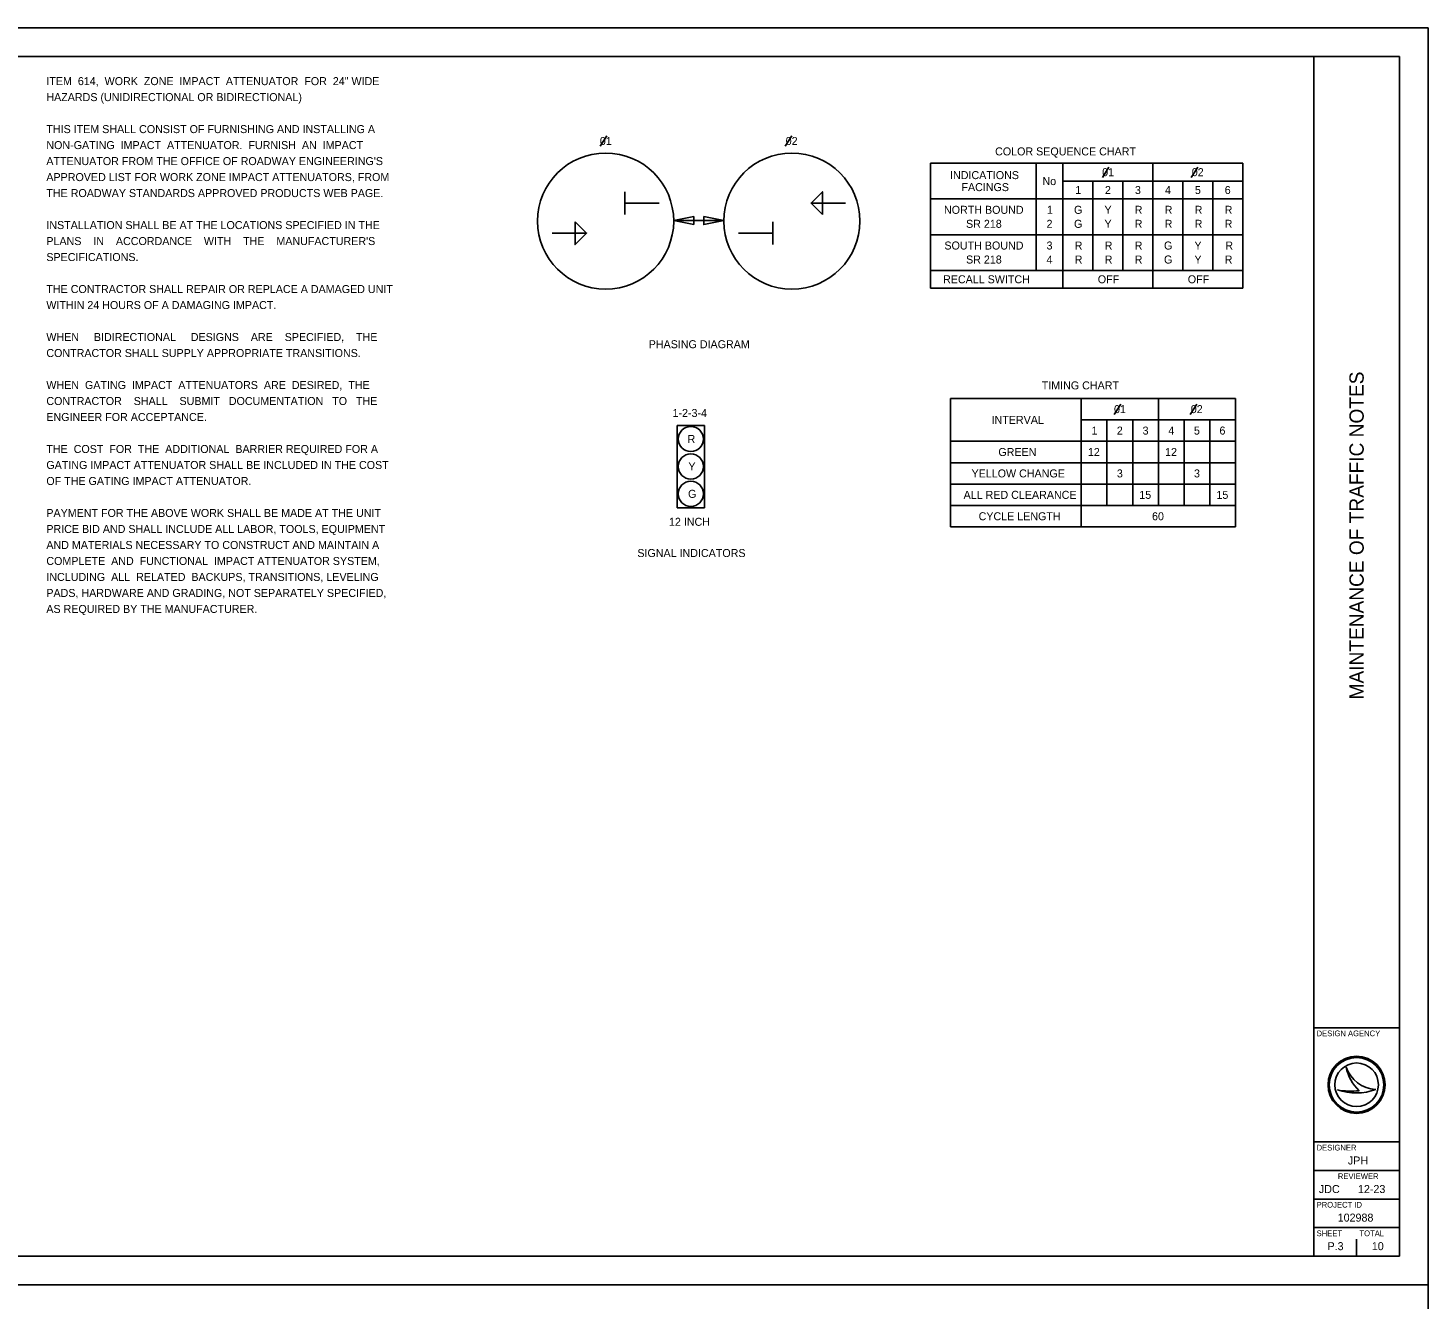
# Model space of a CAD drawing. Extents: x -188 to 680, y 0 to 880.
# Drawn here: x 190 to 680, y 435 to 880 of the extents above; entities that cross this region are included whole.
import ezdxf

# ---------------------------------------------------------------- set-up
doc = ezdxf.new("R2010")
doc.units = 0
for name, color, linetype in [('_CIVIL_CONSTRUCTION', 7, 'Continuous'), ('Default', 7, 'Continuous'), ('DR_X_Culvert', 7, 'Continuous'), ('GE_P_Alignment', 7, 'Continuous'), ('GE_P_Alignment_100_Bearings', 7, 'Continuous'), ('GE_P_Alignment_100_Cardinal_Points', 7, 'Continuous'), ('GE_P_Alignment_100_Curve_Data', 7, 'Continuous'), ('TX_X_10', 7, 'Continuous')]:
    doc.layers.add(name, color=color, linetype=linetype)

msp = doc.modelspace()

# ---------------------------------------------------------------- linework, layer by layer
at = {"layer": '_CIVIL_CONSTRUCTION'}
for points in [[(0, 440), (680, 440), (680, 880), (0, 880)], [(0, 0), (680, 0), (680, 440), (0, 440)]]:
    msp.add_lwpolyline(points, close=True, dxfattribs=at)
at = {"layer": 'Default'}
for p, q in [((505.84, 832.64), (505.84, 788.89)), ((505.84, 832.64), (615.22, 832.64)), ((542.84, 832.64), (542.84, 795.14)), ((552.22, 832.64), (552.22, 788.89)), ((583.72, 832.64), (583.72, 788.89)), ((615.22, 832.64), (615.22, 788.89)), ((615.22, 832.64), (615.22, 788.89)), ((552.22, 826.39), (615.22, 826.39)), ((562.72, 826.39), (562.72, 795.14)), ((573.22, 826.39), (573.22, 795.14)), ((594.22, 826.39), (594.22, 795.14)), ((604.72, 826.39), (604.72, 795.14)), ((505.84, 820.14), (615.22, 820.14)), ((505.84, 807.64), (615.22, 807.64)), ((505.84, 795.14), (615.22, 795.14)), ((505.84, 788.89), (615.22, 788.89)), ((512.92, 750.3), (612.64, 750.3)), ((512.92, 750.3), (512.92, 705.3)), ((558.64, 750.3), (558.64, 705.3)), ((585.64, 750.3), (585.64, 712.8)), ((612.64, 750.3), (612.64, 705.3)), ((426.78, 740.82), (417.21, 740.82)), ((417.21, 740.82), (417.21, 711.98)), ((426.78, 711.98), (426.78, 740.82)), ((558.64, 742.8), (612.64, 742.8)), ((567.64, 742.8), (567.64, 712.8)), ((576.64, 742.8), (576.64, 712.8)), ((594.64, 742.8), (594.64, 712.8)), ((603.64, 742.8), (603.64, 712.8)), ((512.92, 735.3), (612.64, 735.3)), ((512.92, 727.8), (612.64, 727.8)), ((512.92, 720.3), (612.64, 720.3)), ((417.21, 711.98), (426.78, 711.98)), ((512.92, 712.8), (612.64, 712.8)), ((512.92, 705.3), (612.64, 705.3))]:
    msp.add_line(p, q, dxfattribs=at)
for centre in [(421.98, 736.09), (421.98, 726.48), (421.98, 716.9)]:
    msp.add_circle(centre, 4.39, dxfattribs=at)
at = {"layer": 'DR_X_Culvert'}
for p, q in [((390.22, 838.6), (392.53, 842.22)), ((455, 838.6), (457.3, 842.22))]:
    msp.add_line(p, q, dxfattribs=at)
at = {"layer": 'GE_P_Alignment'}
for p, q in [((640, 450), (640, 870)), ((640, 530), (670, 530)), ((640, 490), (670, 490)), ((640, 480), (670, 480)), ((640, 470), (670, 470)), ((640, 460), (670, 460))]:
    msp.add_line(p, q, dxfattribs=at)
msp.add_lwpolyline([(30, 870), (670, 870), (670, 450), (30, 450)], close=True, dxfattribs=at)
at = {"layer": 'GE_P_Alignment_100_Bearings'}
for p, q in [((433.49, 812.57), (416.02, 812.57)), ((651.35, 516.19), (651.35, 516.19)), ((655, 510), (655, 510)), ((648.34, 508.19), (648.34, 508.19)), ((661.75, 508.37), (661.75, 508.37)), ((655, 450), (655, 456)), ((647.5, 453.5), (647.5, 453.5))]:
    msp.add_line(p, q, dxfattribs=at)
for centre, radius in [((392.16, 812.4), 23.82), ((457.34, 812.4), 23.82), ((655, 510), 10), ((655, 510), 9.54), ((655, 510), 9.54), ((655, 510), 7.64)]:
    msp.add_circle(centre, radius, dxfattribs=at)
for centre, radius, start, end in [((662.32, 519.95), 11.6, 198.9257, 198.9319), ((666.93, 519.4), 15.91, 191.6379, 191.6421), ((662.32, 519.95), 11.6, 198.9319, 267.1657), ((666.93, 519.4), 15.91, 191.6421, 226.0947), ((654.79, 527.4), 20.26, 251.4576, 290.0832), ((652.96, 533.09), 25.32, 259.4964, 259.4995), ((654.79, 527.4), 20.26, 251.4527, 251.4576), ((652.96, 533.09), 25.32, 259.4995, 276.6672)]:
    msp.add_arc(centre, radius, start, end, dxfattribs=at)
at = {"layer": 'GE_P_Alignment_100_Curve_Data'}
for p, q in [((566.03, 827.69), (568.33, 831.31)), ((597.12, 827.69), (599.43, 831.31)), ((570.2, 744.72), (572.5, 748.34)), ((596.79, 744.72), (599.09, 748.34))]:
    msp.add_line(p, q, dxfattribs=at)
at = {"layer": 'TX_X_10'}
for p, q in [((398.87, 822.68), (398.87, 814.68)), ((410.89, 818.67), (398.87, 818.67)), ((476.07, 818.67), (464.06, 818.67)), ((450.66, 804.17), (450.66, 812.17)), ((373.47, 808.18), (385.48, 808.18)), ((438.65, 808.18), (450.66, 808.18))]:
    msp.add_line(p, q, dxfattribs=at)
for points in [[(468.06, 814.67), (464.06, 818.67), (468.06, 822.67)], [(423.02, 811.17), (416.02, 812.57), (423.02, 813.97)], [(426.49, 813.97), (433.49, 812.57), (426.49, 811.17)], [(381.48, 812.18), (385.48, 808.18), (381.48, 804.18)]]:
    msp.add_lwpolyline(points, close=True, dxfattribs=at)

# ---------------------------------------------------------------- texts
at = {"layer": 'Default'}
for s, p in [('COLOR SEQUENCE CHART', (528.48, 835.39)), ('TIMING CHART', (544.8, 753.47)), ('R', (420.83, 734.69)), ('Y', (421.13, 725.09)), ('G', (421, 715.5)), ('SIGNAL INDICATORS', (403.26, 694.78))]:
    msp.add_text(s, height=2.8, dxfattribs=at).set_placement(p)
at = {"layer": 'DR_X_Culvert'}
msp.add_text('PHASING DIAGRAM', height=2.8, dxfattribs=at).set_placement((407.23, 767.88))
at = {"layer": 'GE_P_Alignment_100_Bearings'}
msp.add_text('MAINTENANCE OF TRAFFIC NOTES', height=5, rotation=90, dxfattribs=at).set_placement((657.5, 644.93))
for s, height, p in [('DESIGN AGENCY', 2, (641, 527)), ('DESIGNER', 2, (641, 487)), ('JPH', 2.8, (651.97, 482.1)), ('REVIEWER', 2, (648.44, 477)), ('JDC', 2.8, (641.82, 472.1)), ('12-23', 2.8, (655.49, 472.1)), ('PROJECT ID', 2, (641, 467)), ('102988', 2.8, (648.39, 462.1)), ('SHEET', 2, (641, 457)), ('TOTAL', 2, (656, 457)), ('P.3', 2.8, (644.82, 452.1)), ('10', 2.8, (660.34, 452.1))]:
    msp.add_text(s, height=height, dxfattribs=at).set_placement(p)
at = {"layer": 'GE_P_Alignment_100_Cardinal_Points'}
for s, p in [('ITEM  614,  WORK  ZONE  IMPACT  ATTENUATOR  FOR  24" WIDE', (196.4, 860)), ('HAZARDS (UNIDIRECTIONAL OR BIDIRECTIONAL)', (196.4, 854.4)), ('THIS ITEM SHALL CONSIST OF FURNISHING AND INSTALLING A', (196.4, 843.2)), ('NON-GATING  IMPACT  ATTENUATOR.  FURNISH  AN  IMPACT', (196.4, 837.6)), ("ATTENUATOR FROM THE OFFICE OF ROADWAY ENGINEERING'S", (196.4, 832)), ('APPROVED LIST FOR WORK ZONE IMPACT ATTENUATORS, FROM', (196.4, 826.4)), ('THE ROADWAY STANDARDS APPROVED PRODUCTS WEB PAGE.', (196.4, 820.8)), ('INSTALLATION SHALL BE AT THE LOCATIONS SPECIFIED IN THE', (196.4, 809.6)), ("PLANS    IN    ACCORDANCE    WITH    THE    MANUFACTURER'S", (196.4, 804)), ('SPECIFICATIONS.', (196.4, 798.4)), ('THE CONTRACTOR SHALL REPAIR OR REPLACE A DAMAGED UNIT', (196.4, 787.2)), ('WITHIN 24 HOURS OF A DAMAGING IMPACT.', (196.4, 781.6)), ('WHEN     BIDIRECTIONAL     DESIGNS    ARE    SPECIFIED,    THE', (196.4, 770.4)), ('CONTRACTOR SHALL SUPPLY APPROPRIATE TRANSITIONS.', (196.4, 764.8)), ('WHEN  GATING  IMPACT  ATTENUATORS  ARE  DESIRED,  THE', (196.4, 753.6)), ('CONTRACTOR    SHALL    SUBMIT   DOCUMENTATION   TO   THE', (196.4, 748)), ('ENGINEER FOR ACCEPTANCE.', (196.4, 742.4)), ('THE  COST  FOR  THE  ADDITIONAL  BARRIER REQUIRED FOR A', (196.4, 731.2)), ('GATING IMPACT ATTENUATOR SHALL BE INCLUDED IN THE COST', (196.4, 725.6)), ('OF THE GATING IMPACT ATTENUATOR.', (196.4, 720)), ('PAYMENT FOR THE ABOVE WORK SHALL BE MADE AT THE UNIT', (196.4, 708.8)), ('PRICE BID AND SHALL INCLUDE ALL LABOR, TOOLS, EQUIPMENT', (196.4, 703.2)), ('AND MATERIALS NECESSARY TO CONSTRUCT AND MAINTAIN A', (196.4, 697.6)), ('COMPLETE  AND  FUNCTIONAL  IMPACT ATTENUATOR SYSTEM,', (196.4, 692)), ('INCLUDING  ALL  RELATED  BACKUPS, TRANSITIONS, LEVELING', (196.4, 686.4)), ('PADS, HARDWARE AND GRADING, NOT SEPARATELY SPECIFIED,', (196.4, 680.8)), ('AS REQUIRED BY THE MANUFACTURER.', (196.4, 675.2))]:
    msp.add_text(s, height=2.8, dxfattribs=at).set_placement(p)
at = {"layer": 'GE_P_Alignment_100_Curve_Data'}
for s, p in [('01', (390.13, 839.03)), ('02', (455.18, 839.03)), ('INDICATIONS', (512.71, 827.09)), ('01', (565.94, 828.12)), ('02', (597.31, 828.12)), ('FACINGS', (516.7, 822.89)), ('No', (545.06, 824.99)), ('1', (556.55, 821.87)), ('2', (566.92, 821.87)), ('3', (577.43, 821.87)), ('4', (587.93, 821.87)), ('5', (598.4, 821.87)), ('6', (608.85, 821.87)), ('NORTH BOUND', (510.59, 814.94)), ('1', (546.62, 814.94)), ('G', (556.09, 814.94)), ('Y', (566.75, 814.94)), ('R', (577.33, 814.94)), ('R', (587.83, 814.94)), ('R', (598.33, 814.94)), ('R', (608.83, 814.94)), ('SR 218', (518.31, 810.04)), ('2', (546.49, 810.04)), ('G', (556.09, 810.04)), ('Y', (566.75, 810.04)), ('R', (577.33, 810.04)), ('R', (587.83, 810.04)), ('R', (598.33, 810.04)), ('R', (608.83, 810.04)), ('SOUTH BOUND', (510.74, 802.44)), ('3', (546.49, 802.44)), ('R', (556.33, 802.44)), ('R', (566.83, 802.44)), ('R', (577.33, 802.44)), ('G', (587.59, 802.44)), ('Y', (598.25, 802.44)), ('R', (609.05, 802.44)), ('SR 218', (518.31, 797.54)), ('4', (546.49, 797.54)), ('R', (556.33, 797.54)), ('R', (566.83, 797.54)), ('R', (577.33, 797.54)), ('G', (587.59, 797.54)), ('Y', (598.25, 797.54)), ('R', (608.83, 797.54)), ('RECALL SWITCH', (510.27, 790.62)), ('OFF', (564.43, 790.62)), ('OFF', (595.93, 790.62)), ('1-2-3-4', (415.57, 743.81)), ('01', (570.1, 745.15)), ('02', (596.97, 745.15)), ('INTERVAL', (527.24, 741.4)), ('1', (562.22, 737.65)), ('2', (571.09, 737.65)), ('3', (580.1, 737.65)), ('4', (589.1, 737.65)), ('5', (598.07, 737.65)), ('6', (607.01, 737.65)), ('GREEN', (529.62, 730.15)), ('12', (560.97, 730.15)), ('12', (587.97, 730.15)), ('YELLOW CHANGE', (520.23, 722.65)), ('3', (571.1, 722.65)), ('3', (598.1, 722.65)), ('ALL RED CLEARANCE', (517.45, 715.15)), ('15', (578.95, 715.15)), ('15', (605.95, 715.15)), ('12 INCH', (414.33, 705.71)), ('CYCLE LENGTH', (522.71, 707.65)), ('60', (583.41, 707.65))]:
    msp.add_text(s, height=2.8, dxfattribs=at).set_placement(p)

doc.saveas('drawing.dxf')
